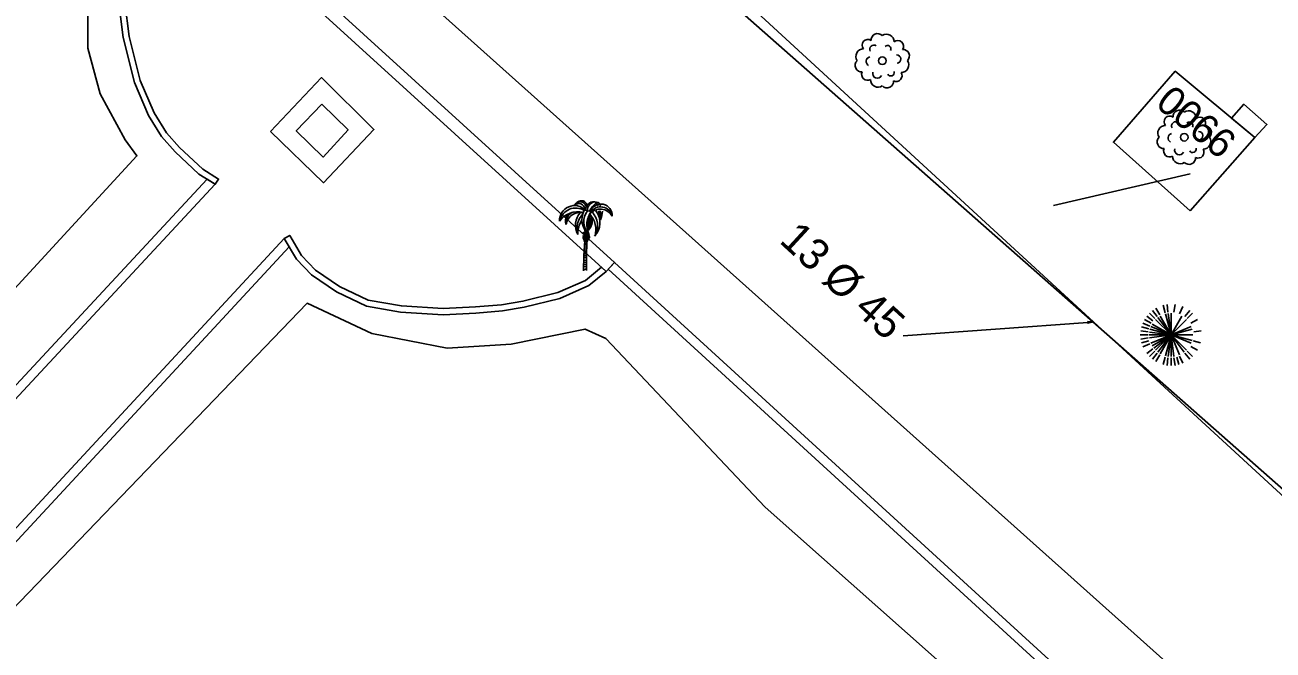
# Model space of a CAD drawing. Extents: x 343997 to 344255, y 298512 to 298767.
# Drawn here: x 344111.1 to 344151.36, y 298671.53 to 298691.69 of the extents above; entities that cross this region are included whole.
import ezdxf

# ---------------------------------------------------------------- set-up
doc = ezdxf.new("R2010")
doc.units = 0
for name, color, linetype in [('Default', 7, 'Continuous'), ('DH_CADRE-CARTOUCHE', 7, 'Continuous'), ('DH_TEXTE', 7, 'Continuous'), ('DIR-Projet VRD1', 7, 'Continuous'), ('GO_DALLE', 7, 'Continuous'), ('O-Projet New VRD', 7, 'Continuous'), ('PC_REBAR', 7, 'Continuous'), ('PS_PLATE', 7, 'Continuous')]:
    doc.layers.add(name, color=color, linetype=linetype)

# ---------------------------------------------------------------- blocks, each defined once
blk = doc.blocks.new('ARB1')
at = {"layer": 'Default'}
blk.add_circle((0, 0), 0.0122, dxfattribs=at)
for centre, radius, start, end in [((-0.0153, 0.0664), 0.0211, 43.6925, 183.5969), ((0.0139, 0.0613), 0.0241, 358.4583, 125.1928), ((-0.0471, 0.0503), 0.0183, 53.9554, 222.2066), ((-0.0276, 0.037), 0.0134, 52.4396, 209.5496), ((0.0164, 0.038), 0.0112, 330.5895, 133.7127), ((0.0501, 0.0468), 0.0183, 325.1444, 131.0175), ((-0.0613, 0.0139), 0.0241, 88.4583, 215.1928), ((-0.0373, -0.0024), 0.0149, 103.7092, 242.3465), ((0.0458, 0.0052), 0.0137, 276.6214, 88.967), ((0.0613, -0.0139), 0.0241, 268.4583, 35.1928), ((0.0664, 0.0153), 0.0211, 313.6925, 93.5969), ((-0.0664, -0.0153), 0.0211, 133.6925, 273.5969), ((-0.0478, -0.0443), 0.019, 155.2243, 300.9377), ((-0.0163, -0.042), 0.0148, 159.5371, 338.1663), ((0.0271, -0.038), 0.0112, 210.5895, 13.7127), ((0.0448, -0.0483), 0.0188, 243.1323, 33.0297), ((-0.0139, -0.0613), 0.0241, 178.4583, 305.1928), ((0.0153, -0.0664), 0.0211, 223.6925, 3.5969)]:
    blk.add_arc(centre, radius, start, end, dxfattribs=at)
blk = doc.blocks.new('ARB2')
at = {"layer": 'Default'}
for p, q in [((-0.0356, 0.0642), (-0.0481, 0.0858)), ((-0.0181, 0.0716), (-0.0244, 0.0956)), ((-0.0088, 0.0736), (-0.0119, 0.0983)), ((0.0106, 0.0736), (0.0144, 0.0983)), ((0.0287, 0.0684), (0.0388, 0.0914)), ((-0.0631, 0.0373), (-0.0844, 0.0497)), ((-0.0575, 0.0453), (-0.0775, 0.0605)), ((-0.0513, 0.0525), (-0.0688, 0.0702)), ((-0.0438, 0.0589), (-0.0588, 0.0786)), ((0.0456, 0.0589), (0.0612, 0.0786)), ((0.0531, 0.0525), (0.0706, 0.0702)), ((0.065, 0.0373), (0.0862, 0.0497)), ((-0.0731, 0), (-0.0981, 0)), ((-0.0725, 0.01), (-0.0969, 0.0133)), ((-0.0706, 0.0195), (-0.0944, 0.0259)), ((-0.0675, 0.0286), (-0.09, 0.0381)), ((0.0744, 0.01), (0.0987, 0.0133)), ((-0.0725, -0.01), (-0.0969, -0.0133)), ((-0.0706, -0.0195), (-0.0944, -0.0259)), ((-0.0675, -0.0287), (-0.09, -0.0383)), ((0.065, -0.0373), (0.0862, -0.0498)), ((0.0725, -0.0195), (0.0963, -0.0259)), ((-0.0575, -0.0455), (-0.0775, -0.0605)), ((-0.0513, -0.0527), (-0.0688, -0.0702)), ((-0.0438, -0.0591), (-0.0588, -0.0787)), ((-0.0356, -0.0644), (-0.0481, -0.0859)), ((-0.0181, -0.0717), (-0.0244, -0.0956)), ((-0.0088, -0.0737), (-0.0119, -0.0983)), ((0.0013, -0.0741), (0.0013, -0.0989)), ((0.0106, -0.0737), (0.0144, -0.0983)), ((0.02, -0.0717), (0.0263, -0.0956)), ((0.0287, -0.0686), (0.0388, -0.0916)), ((0.0456, -0.0591), (0.0612, -0.0787)), ((0.0531, -0.0527), (0.0706, -0.0702))]:
    blk.add_line(p, q, dxfattribs=at)
for points in [[(-0.0688, 0.0091), (0.0013, 0), (-0.0338, 0.0608)], [(-0.0487, 0.0495), (0.0013, 0), (-0.0669, 0.0181)], [(-0.0419, 0.0556), (0.0013, 0), (-0.0638, 0.0269)], [(-0.0169, 0.0677), (0.0013, 0), (-0.06, 0.035)], [(0.0013, 0.0008), (0.0013, 0), (-0.0081, 0.0695)], [(0.0362, 0.0608), (0.0013, 0), (0.0013, 0.0702)], [(0.0656, 0.0269), (0.0013, 0), (0.0506, 0.0495)], [(-0.0487, -0.0497), (0.0013, 0), (-0.0694, 0)], [(-0.0638, -0.0269), (0.0013, 0), (-0.0688, -0.0092)], [(-0.0169, -0.0678), (0.0013, 0), (-0.06, -0.0352)], [(-0.0544, -0.0428), (0.0013, 0), (-0.0338, -0.0608)], [(-0.0081, -0.0695), (0.0013, 0), (-0.0419, -0.0558)], [(0.0013, -0.0702), (0.0013, 0), (0, 0)], [(0.0688, 0.0181), (0.0013, 0), (0.0713, 0)], [(0.0438, -0.0558), (0.0013, 0), (0.0656, -0.0269)], [(0.0506, -0.0497), (0.0013, 0), (0.0688, -0.0181)], [(0.01, -0.0695), (0.0013, 0), (0.0281, -0.0648)], [(0.0019, 0), (0.0013, 0), (0.0013, -0.0009)]]:
    blk.add_lwpolyline(points, dxfattribs=at)
blk = doc.blocks.new('PALMIER')
at = {"layer": 'Default'}
for p, q in [((0.007, 0.1023), (-0.002, 0.1046)), ((-0.0016, 0.1111), (0.0072, 0.1097)), ((0.006, 0.053), (-0.0047, 0.0516)), ((-0.0036, 0.077), (0.0064, 0.0807)), ((0.0066, 0.0879), (-0.0031, 0.0865)), ((-0.0027, 0.0942), (0.0068, 0.0953)), ((-0.0062, 0.0035), (0.0058, 0.0076)), ((0.0058, 0.0159), (-0.0059, 0.0156)), ((-0.0057, 0.024), (0.0058, 0.0243)), ((0.0058, 0.0341), (-0.0054, 0.0323)), ((-0.0051, 0.0409), (0.0059, 0.0425))]:
    blk.add_line(p, q, dxfattribs=at)
blk.add_lwpolyline([(-0.0044, 0.0591), (0.0061, 0.0593), (0.0062, 0.0664), (-0.0041, 0.0672)], dxfattribs=at)
for centre, radius, start, end in [((-0.0427, 0.2014), 0.0606, 43.7538, 181.6042), ((-0.0379, 0.1861), 0.066, 58.0609, 166.7618), ((-0.0119, 0.25), 0.0329, 122.4892, 158.9053), ((-0.0196, 0.2528), 0.0242, 4.6636, 154.2427), ((-0.0249, 0.2465), 0.0236, 4.3858, 134.352), ((-0.0156, 0.2558), 0.026, 21.2278, 122.4892), ((0.039, 0.2418), 0.0379, 113.9098, 175.4727), ((0.039, 0.2418), 0.0379, 113.9098, 175.4727), ((0.0433, 0.2437), 0.0332, 97.2666, 184.0929), ((0.1052, 0.1956), 0.0976, 126.8275, 153.3081), ((0.0636, 0.2223), 0.0459, 356.3044, 159.1426), ((0.0629, 0.2092), 0.0477, 12.2494, 148.4563), ((0.0357, 0.2315), 0.0459, 69.2234, 105.0038), ((-0.0152, 0.1926), 0.0754, 51.3892, 54.6634), ((-0.1014, 0.1466), 0.1819, 37.7085, 40.6574), ((-0.0251, 0.2185), 0.0885, 28.6142, 37.2383), ((0.0508, 0.2682), 0.00691, 35.4622, 126.8275), ((-0.0048, 0.2285), 0.0752, 25.9612, 35.4622), ((-0.0287, 0.1433), 0.0935, 76.8807, 142.9442), ((-0.0298, 0.2021), 0.0491, 151.2749, 199.7359), ((-0.0191, 0.177), 0.0575, 78.6557, 171.4922), ((-0.0318, 0.1955), 0.0441, 119.2251, 188.9038), ((0.0377, 0.1821), 0.0768, 136.853, 208.9638), ((0.057, 0.1687), 0.0895, 137.8747, 194.5133), ((0.0671, 0.1493), 0.0966, 145.6563, 182.5945), ((0.064, 0.2063), 0.0767, 153.2285, 230.2541), ((0.0679, 0.197), 0.0731, 142.4971, 222.4211), ((0, 0.2373), 0.00573, 81.8892, 144.4453), ((-0.0182, 0.1095), 0.1349, 71.5132, 81.8892), ((0.0306, 0.2506), 0.0261, 198.8183, 199.9044), ((0.0989, 0.184), 0.0917, 144.1283, 203.5706), ((0.0563, 0.1714), 0.0483, 137.337, 173.0404), ((0.0322, 0.1915), 0.023, 121.5714, 182.4317), ((2.7823, 0.0039), 2.7774, 175.6208, 176.7014), ((0.0325, 0.2055), 0.0223, 141.9977, 191.6592), ((0.042, 0.1776), 0.0361, 125.2003, 146.531), ((0.0414, 0.2001), 0.0306, 136.5986, 162.2103), ((0.0372, 0.1986), 0.0249, 133.2601, 172.8951), ((-0.0764, 0.1855), 0.0939, 344.9923, 16.0405), ((-0.0403, 0.1944), 0.063, 329.6083, 26.821), ((-0.0287, 0.201), 0.0575, 317.9696, 12.4803), ((0.0609, 0.1916), 0.0559, 29.7072, 139.4934), ((-0.0544, 0.1637), 0.0978, 345.0198, 41.2878), ((-0.0338, 0.1796), 0.0844, 47.1184, 50.2648), ((-0.0338, 0.1796), 0.0844, 334.2104, 41.3357), ((-0.0152, 0.1926), 0.0754, 315.2889, 39.1656), ((-0.1727, 0.1741), 0.237, 7.7396, 16.5083), ((-0.0251, 0.2185), 0.0885, 351.03, 14.848), ((-0.0484, 0.2461), 0.1182, 339.5014, 356.7342), ((-0.0285, 0.1344), 0.0284, 348.9674, 47.5038), ((2.4236, -0.046), 2.4303, 175.1176, 178.9434), ((-0.0275, 0.1529), 0.0286, 2.2916, 36.7742), ((-0.0586, 0.1323), 0.0604, 357.2226, 24.4977), ((-0.026, 0.1395), 0.0322, 340.1414, 25.8645), ((0.0212, 0.1553), 0.018, 167.086, 185.7383), ((2.7948, 0.0208), 2.789, 177.2861, 180.4137), ((0.0388, 0.1745), 0.0282, 133.7373, 173.6287), ((0.0832, 0.1435), 0.0791, 142.3775, 156.4217), ((0.0255, 0.1864), 0.0149, 111.1145, 166.1173), ((-0.0205, 0.1197), 0.0169, 353.506, 55.1211), ((-0.0721, 0.1091), 0.0712, 9.1555, 26.6687), ((-0.0349, 0.1239), 0.0371, 353.6232, 41.3494), ((0.0287, 0.1204), 0.0266, 120.4076, 191.5492), ((0.0343, 0.1162), 0.0295, 120.978, 179.2294), ((0.0244, 0.1306), 0.0167, 110.7357, 185.3567), ((0.0507, 0.1019), 0.045, 131.0176, 160.1686)]:
    blk.add_arc(centre, radius, start, end, dxfattribs=at)

msp = doc.modelspace()

# ---------------------------------------------------------------- linework, layer by layer
at = {"layer": 'DH_CADRE-CARTOUCHE'}
for points in [[(344122.649, 298749.916), (344119.175, 298746.216), (344104.333, 298729.921), (344103.629, 298728.425), (344103.178, 298726.908), (344102.994, 298725.349), (344103.009, 298724.152), (344103.293, 298722.366), (344103.622, 298721.156), (344104.336, 298719.642), (344105.154, 298718.475), (344128.542, 298697.099), (344156.76, 298672.229), (344158.923, 298671.699), (344160.816, 298671.605), (344163.478, 298672.279), (344165.611, 298673.484), (344167.1, 298674.65), (344168.229, 298675.97), (344184.084, 298692.584)], [(344066.641, 298688.625), (344090.832, 298714.382), (344091.46, 298714.944), (344092.393, 298715.535), (344093.275, 298715.95), (344094.045, 298716.161), (344094.983, 298716.297), (344095.976, 298716.287), (344096.908, 298716.148), (344097.634, 298715.942), (344098.359, 298715.623), (344098.865, 298715.357), (344099.332, 298715.052), (344124.372, 298692.186), (344148.812, 298670.333)]]:
    msp.add_lwpolyline(points, dxfattribs=at)
at = {"layer": 'DH_TEXTE'}
msp.add_line((344144.279, 298685.866), (344148.684, 298686.887), dxfattribs=at)
at = {"layer": 'DIR-Projet VRD1'}
msp.add_line((344129.041, 298697.326), (344161.307, 298667.622), dxfattribs=at)
at = {"layer": 'GO_DALLE'}
for points in [[(344119.026, 298688.255), (344120.735, 298686.6), (344122.356, 298688.316), (344120.662, 298689.995)], [(344148.685, 298685.7), (344146.205, 298687.907), (344148.199, 298690.2), (344150.764, 298688.06)], [(344120.676, 298689.131), (344119.853, 298688.272), (344120.715, 298687.431), (344121.526, 298688.303)], [(344150.764, 298688.06), (344151.158, 298688.481), (344150.409, 298689.131), (344150.019, 298688.681)]]:
    msp.add_lwpolyline(points, close=True, dxfattribs=at)
at = {"layer": 'O-Projet New VRD'}
msp.add_lwpolyline([(344145.381, 298682.097), (344139.425, 298681.661)], dxfattribs=at)
msp.add_lwpolyline([(344145.379, 298682.126), (344145.56, 298682.11), (344145.383, 298682.067)], close=True, dxfattribs=at)
at = {"layer": 'PC_REBAR'}
for points in [[(344115.386, 298697.034), (344095.685, 298715.142), (344067.379, 298684.161), (344067.261, 298683.991), (344067.218, 298683.388), (344067.403, 298682.745), (344071.702, 298678.318), (344092.045, 298659.877), (344116.981, 298686.713), (344117.24, 298686.552), (344092.063, 298659.455), (344071.494, 298678.102), (344067.135, 298682.59), (344066.915, 298683.356), (344066.967, 298684.094), (344067.145, 298684.349), (344095.667, 298715.566), (344115.589, 298697.255)], [(344129.915, 298683.811), (344149.954, 298665.484), (344120.649, 298634.816), (344119.758, 298634.843), (344094.693, 298657.614), (344119.626, 298684.533), (344119.467, 298684.803), (344094.267, 298657.595), (344119.638, 298634.546), (344120.774, 298634.512), (344150.383, 298665.499), (344130.117, 298684.033)]]:
    msp.add_lwpolyline(points, close=True, dxfattribs=at)
for points in [[(344091.233, 298661.951), (344078.543, 298673.539), (344067.651, 298683.727), (344070.267, 298686.633), (344094.013, 298711.291), (344094.723, 298711.636), (344095.462, 298711.65), (344096.516, 298711.35), (344098.055, 298710.152), (344102.625, 298705.772), (344106.459, 298702.051), (344111.683, 298696.937), (344113.434, 298695.237), (344113.122, 298693.176), (344113.133, 298690.945), (344113.53, 298689.467), (344114.335, 298687.988), (344114.712, 298687.466), (344091.233, 298661.951)], [(344108.757, 298670.826), (344120.202, 298682.712), (344122.289, 298681.737), (344124.72, 298681.269), (344126.782, 298681.391), (344129.166, 298681.878), (344129.834, 298681.573), (344134.972, 298676.138), (344141.382, 298670.447)]]:
    msp.add_lwpolyline(points, dxfattribs=at)
at = {"layer": 'PS_PLATE'}
for points in [[(344115.32, 298696.96), (344115.589, 298697.255), (344130.117, 298684.033), (344129.848, 298683.737)], [(344129.848, 298683.737), (344129.29, 298683.281), (344128.353, 298682.867), (344127.202, 298682.582), (344126.5, 298682.465), (344125.648, 298682.397), (344124.59, 298682.342), (344123.219, 298682.428), (344122.112, 298682.617), (344121.145, 298683.081), (344120.339, 298683.63), (344119.861, 298684.132), (344119.467, 298684.803), (344119.64, 298684.904), (344120.022, 298684.253), (344120.469, 298683.784), (344121.245, 298683.254), (344122.173, 298682.809), (344123.242, 298682.627), (344124.591, 298682.542), (344125.635, 298682.597), (344126.475, 298682.664), (344127.162, 298682.778), (344128.288, 298683.056), (344129.184, 298683.452), (344129.698, 298683.873)]]:
    msp.add_lwpolyline(points, close=True, dxfattribs=at)
msp.add_lwpolyline([(344114.324, 298692.414), (344114.467, 298691.322), (344114.82, 298689.897), (344115.266, 298688.858), (344115.671, 298688.21), (344116.089, 298687.743), (344116.837, 298687.038), (344117.346, 298686.721), (344117.24, 298686.552), (344116.714, 298686.878), (344115.945, 298687.603), (344115.51, 298688.09), (344115.088, 298688.765), (344114.63, 298689.833), (344114.27, 298691.284), (344114.125, 298692.395)], dxfattribs=at)

# ---------------------------------------------------------------- block references
at = {"layer": 'PC_REBAR'}
for name, p, xscale, yscale in [('ARB1', (344138.754, 298690.538), 10, 10), ('ARB1', (344148.493, 298688.067), 10, 10), ('PALMIER', (344129.167, 298683.768), 8, 8), ('ARB2', (344148.055, 298681.693), 10, 10)]:
    msp.add_blockref(name, p, dxfattribs=dict(at, xscale=xscale, yscale=yscale))

# ---------------------------------------------------------------- texts
at = {"layer": 'DH_TEXTE'}
msp.add_text('0066', height=0.9308, rotation=320.3665, dxfattribs=at).set_placement((344147.522, 298689.094))
at = {"layer": 'O-Projet New VRD'}
msp.add_text('13 Ø 45', height=1.0003, rotation=317.3672, dxfattribs=at).set_placement((344135.396, 298684.696))

doc.saveas('drawing.dxf')
